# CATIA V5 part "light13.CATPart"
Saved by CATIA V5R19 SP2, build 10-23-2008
Part number: light13
Bounding box of the stored display mesh (mm): x -1261.214 to -486.867, y -622.132 to 622.132, z 560.173 to 628.472
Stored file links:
  C:\BEHROOZ\catia learning\tarh haye mashin\hb\light13.CATPart
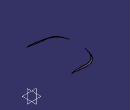
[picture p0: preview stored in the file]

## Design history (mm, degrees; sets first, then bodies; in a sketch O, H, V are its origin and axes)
Body1 (main body)
  Set1
    DatumSurface1
    ThickSurface1: Surface DatumSurface1, TopOffset 1, BotOffset 0
    DatumSurface2
    ThickSurface2: Surface DatumSurface2, TopOffset 1, BotOffset 0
